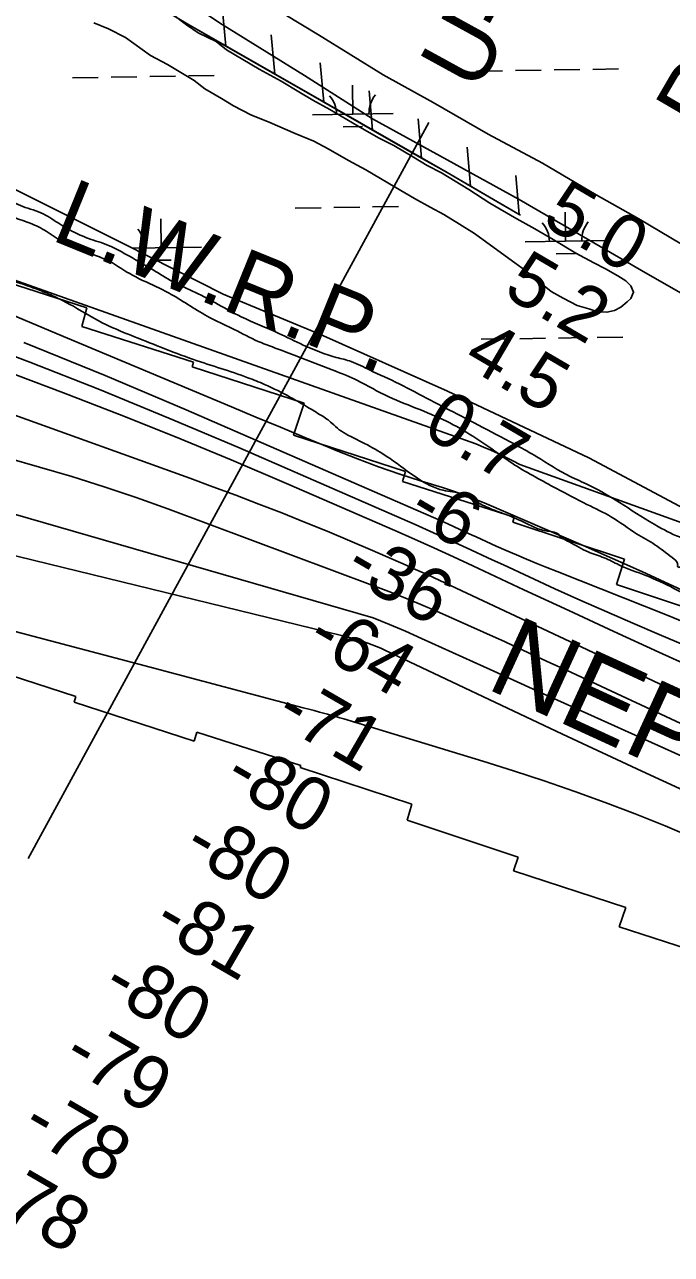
# Model space of a CAD drawing. Extents: x 3855477 to 3893699, y 299188 to 325115.
# Drawn here: x 3860091 to 3860894, y 316616 to 318142 of the extents above; entities that cross this region are included whole.
import ezdxf

# ---------------------------------------------------------------- set-up
doc = ezdxf.new("R2010")
doc.units = 0
for name, color, linetype in [('V-CHAN-NAID', 7, 'Continuous'), ('V-LEVE-TOET', 7, 'Continuous'), ('V-RIVR-EDGE', 7, 'Continuous'), ('V-RIVR-RANG', 7, 'Continuous'), ('V-RIVR-RANG-IDEN', 7, 'Continuous'), ('V-RRAP-FSHR', 7, 'Continuous'), ('V-RRAP-RVMT', 7, 'Continuous'), ('V-RRAP-RVMT-IDEN', 7, 'Continuous'), ('V-TOPO-DPTH', 7, 'Continuous'), ('V-TOPO-MAJR', 7, 'Continuous'), ('V-TOPO-MINR', 7, 'Continuous'), ('V-TOPO-SHOR', 7, 'Continuous'), ('V-TOPO-WATR', 7, 'Continuous'), ('V-TOPO-WATR-IDEN', 7, 'Continuous'), ('V-WETL-SWMP', 7, 'Continuous')]:
    doc.layers.add(name, color=color, linetype=linetype)

msp = doc.modelspace()

# ---------------------------------------------------------------- linework, layer by layer
at = {"layer": 'V-LEVE-TOET'}
for points in [[(3860906.5, 317869.1), (3860853.5, 317900.8), (3860800.4, 317930.4), (3860733.8, 317969.6), (3860666.5, 318005.7), (3860598.2, 318045), (3860536.2, 318079.5), (3860455.9, 318128.9), (3860372.4, 318180), (3860276.4, 318242.8), (3860194, 318291.7), (3860139.8, 318321.8), (3860102.5, 318340.2), (3860072.5, 318352.6), (3860019.4, 318370.1), (3859933.5, 318397.4), (3859855.1, 318425.7), (3859732.9, 318467.1), (3859678.2, 318484), (3859605.4, 318501.7), (3859553.3, 318515.5), (3859517.4, 318516.9), (3859513.2, 318517.2)], [(3859514.1, 318457), (3859544.7, 318456.4), (3859632.8, 318439.6), (3859717, 318409.2), (3859829.1, 318369.4), (3859948.7, 318332.3), (3860037.2, 318309.7), (3860100.9, 318287.9), (3860151.4, 318261.5), (3860238.5, 318206.7), (3860336.1, 318141.8), (3860438.5, 318078.4), (3860523, 318024.7), (3860615.5, 317974), (3860704.8, 317924.5), (3860792.5, 317873.9), (3860861.8, 317833.6), (3860920.6, 317800.2)]]:
    msp.add_lwpolyline(points, dxfattribs=at)
at = {"layer": 'V-RIVR-EDGE'}
for points in [[(3859519.3, 318133.3), (3859529.1, 318128.1), (3859557.8, 318117.3), (3859589.2, 318096.9), (3859608.3, 318091.7), (3859632.6, 318087.2), (3859655.7, 318083.2), (3859677.6, 318079.1), (3859695.1, 318076.3), (3859736.6, 318066.2), (3859764.5, 318061.4), (3859790.3, 318051.8), (3859824.2, 318038.5), (3859868.4, 318020.1), (3859890.7, 318012), (3859919.3, 318000.8), (3859946.4, 317985.2), (3859972.3, 317972.4), (3859987.4, 317966), (3859998.9, 317963.2), (3860007.3, 317958.4), (3860026.8, 317947.5), (3860045.9, 317937.5), (3860071.4, 317923.9), (3860094.9, 317913.9), (3860108.4, 317909.5), (3860130.3, 317897.1), (3860149.8, 317885.5), (3860170.5, 317876.3), (3860195.2, 317867.8), (3860221.1, 317854.2), (3860250.5, 317837.4), (3860275.2, 317822.6), (3860303, 317809.4), (3860359.6, 317779.3), (3860406.5, 317758.5), (3860436.8, 317744.1), (3860477.8, 317728.8), (3860496.5, 317723.6), (3860519.2, 317713.2), (3860555.8, 317696), (3860594.8, 317675.5), (3860632.3, 317656.3), (3860676.4, 317633.1), (3860726.6, 317605.5), (3860768, 317581.1), (3860790.7, 317570.6), (3860877.8, 317518.6), (3860907.7, 317504.6), (3860923.6, 317499.8), (3860947.5, 317491.7), (3860980.9, 317479.3), (3861011.2, 317471.3), (3861035.1, 317464.4), (3861065.4, 317456), (3861094, 317449.1), (3861112.8, 317445.1), (3861139.1, 317440.3), (3861167.3, 317430.2), (3861205.2, 317422.2), (3861236.2, 317418.9), (3861259.4, 317418), (3861273.7, 317417.2), (3861300, 317410), (3861325.9, 317397.5), (3861341.8, 317391.5), (3861353.7, 317387.9), (3861368.5, 317388.7), (3861377.7, 317388.7), (3861664.7, 317282.7), (3861681.1, 317276.7), (3861681.1, 317274.3), (3861687, 317270.7), (3861700.2, 317265.1), (3861705.7, 317256.7), (3861715.7, 317246.3), (3861721.2, 317241.5), (3861723.2, 317234.4), (3861726.4, 317227.6), (3861750.6, 317208), (3861757.4, 317197.6), (3861762.5, 317188.8), (3861767.3, 317187.2), (3861780.1, 317185.6), (3861788, 317178), (3861803.1, 317165.2), (3861810.3, 317151.6), (3861809.8, 317139.7), (3861814.2, 317132.9), (3861819.8, 317124.1), (3861817.3, 317108.6), (3861814.5, 317094.2), (3861799.4, 317086.7), (3861786.6, 317080.8), (3861777, 317076.8), (3861766.2, 317064.1), (3861761.8, 317062.9), (3861758.7, 317067.3), (3861753.9, 317083.2), (3861749.9, 317087.2), (3861742.8, 317089.6), (3861728.4, 317090.1), (3861720.1, 317091.3), (3861710.5, 317097.3), (3861701.4, 317107.7), (3861698.2, 317118), (3861695, 317124), (3861685.5, 317130.4), (3861670.3, 317131.3), (3861652.8, 317132.5), (3861648.4, 317134.1), (3861621.8, 317148.9), (3861610.2, 317154.5), (3861601.8, 317155.4), (3861592.3, 317158.2), (3861585.1, 317163.8), (3861576.8, 317171), (3861567.2, 317173.4), (3861541.3, 317180.2), (3861520.6, 317180.7), (3861509.8, 317179.9), (3861487.1, 317186.7), (3861457.3, 317196.8), (3861452.1, 317196), (3861445.3, 317191.2), (3861444.5, 317182.8), (3861448.1, 317178.4), (3861469.6, 317166.8), (3861511, 317148.8), (3861530.5, 317141.2), (3861552.8, 317132.4), (3861597, 317112.7)], [(3861161.1, 317323), (3861105.3, 317341.9), (3861095.4, 317346.7), (3861067.1, 317358.7), (3861040.4, 317369.2), (3861025.7, 317379.2), (3861011, 317386.8), (3860989.9, 317398.4), (3860974.8, 317402), (3860962, 317408), (3860930.6, 317424.4), (3860862.1, 317458.1), (3860828.7, 317471.3), (3860810.4, 317480.1), (3860790.5, 317487.3), (3860767, 317499.8), (3860758.6, 317504.6), (3860752.3, 317510.2), (3860744.3, 317512.6), (3860728, 317516.2), (3860714, 317522.6), (3860687.4, 317534.2), (3860666.2, 317542.3), (3860648.7, 317551.5), (3860633.2, 317559.5), (3860610.5, 317563.9), (3860578.7, 317578.7), (3860544.8, 317603.1), (3860519.8, 317618.3), (3860492.3, 317632.4), (3860481.6, 317638.8), (3860472.4, 317647.1), (3860466.1, 317652.3), (3860459.3, 317656.7), (3860442.2, 317667.1), (3860421.1, 317679.2), (3860388.8, 317695.2), (3860368.1, 317703.6), (3860300.8, 317726.1), (3860260.2, 317741.3), (3860222.8, 317756.2), (3860187.4, 317771.8), (3860146.4, 317795), (3860128.1, 317804.2), (3860109.4, 317812.2), (3860044.5, 317834.7), (3859988.3, 317859.6), (3859925.4, 317886.8), (3859887.6, 317901.3), (3859853.8, 317911.7), (3859831.9, 317919.7), (3859802.8, 317933), (3859772.9, 317945.8), (3859734.7, 317960.2), (3859695.3, 317982.6), (3859660.3, 318005.4), (3859631.2, 318017.5), (3859592.2, 318031.9), (3859552, 318048), (3859520.4, 318061)], [(3859768.4, 318041), (3859805.8, 318029), (3859833.7, 318015.8), (3859870.7, 318001.7), (3859904.6, 317989.3), (3859933.6, 317976.1), (3859963.5, 317964), (3859985, 317954), (3860008.5, 317939.6), (3860049.4, 317917.2), (3860076.9, 317902.8), (3860098, 317895.2), (3860117.9, 317885.2), (3860137.8, 317872.3), (3860159.3, 317862.3), (3860181.6, 317854.3), (3860199.9, 317845.9), (3860220.6, 317833.1), (3860254.8, 317816.3), (3860275.5, 317805.5), (3860323.7, 317776.6), (3860351.2, 317763.4), (3860381, 317748.6), (3860409.3, 317737.8), (3860435.2, 317727.7), (3860478.2, 317711.3), (3860508, 317698.1), (3860533.5, 317684.5), (3860610.3, 317651.6), (3860643.8, 317633.2), (3860673.2, 317613.6), (3860699.5, 317595.2), (3860724.9, 317580.4), (3860751.2, 317566), (3860789, 317546.3), (3860819.3, 317530.7), (3860850.7, 317509.9), (3860873.4, 317496.3), (3860894.9, 317480.3), (3860901.6, 317471.5), (3860901.6, 317468.7), (3860907.6, 317469.1), (3860918.7, 317465.1), (3860923.5, 317464.7), (3860931.5, 317464.7), (3860947.8, 317458.7), (3860971.7, 317449), (3860994.8, 317440.6), (3861011.5, 317433.4), (3861011.9, 317431.8), (3861012.3, 317422.2), (3861016.7, 317418.2), (3861031, 317413.8), (3861040.2, 317413.4), (3861052.9, 317411.8), (3861066.4, 317406.2), (3861070, 317402.6), (3861076, 317395), (3861087.9, 317391), (3861099.5, 317390.9), (3861115, 317393.3), (3861126.6, 317391.7), (3861145.7, 317385.6), (3861160.4, 317379.2), (3861170.4, 317373.6), (3861184.7, 317369.6), (3861204.2, 317363.6), (3861220.6, 317357.6), (3861237.3, 317348.7), (3861251.2, 317336.8), (3861264.7, 317323.6), (3861275, 317308.8), (3861281.8, 317303.2), (3861294.5, 317299.2), (3861313.6, 317284.4), (3861329.5, 317269.2), (3861363, 317248.4), (3861390, 317232.8), (3861398.4, 317228.8), (3861402.3, 317222.4), (3861399.9, 317218), (3861392.4, 317214.5), (3861387.2, 317215.3), (3861362.1, 317229.3), (3861300.4, 317260.5), (3861223.6, 317297.8), (3861161.1, 317323)]]:
    msp.add_spline(points, degree=3, dxfattribs=at)
at = {"layer": 'V-RIVR-RANG'}
msp.add_line((3860592.6, 318020.3), (3860095.2, 317106.9), dxfattribs=at)
at = {"layer": 'V-RRAP-FSHR'}
for p, q in [((3860340.8, 318115.1), (3860336.3, 318163.7)), ((3860401.5, 318080.3), (3860397.1, 318129)), ((3860462.3, 318045.6), (3860457.8, 318094.2)), ((3860523, 318010.8), (3860518.6, 318059.5)), ((3860583.8, 317976.1), (3860579.4, 318024.7)), ((3860644.5, 317941.1), (3860640.3, 317989.8)), ((3860705, 317906), (3860700.9, 317954.6))]:
    msp.add_line(p, q, dxfattribs=at)
for points in [[(3860705.6, 317905.7), (3860615.5, 317958), (3860293.4, 318142.2), (3860158, 318223.3), (3860080.4, 318260.2), (3859675.5, 318399.5)], [(3860340.8, 318115.1), (3860293.4, 318142.2), (3860280.2, 318150.1)], [(3860523, 318010.8), (3860462.3, 318045.6), (3860401.5, 318080.3), (3860340.8, 318115.1)], [(3860583.8, 317976.1), (3860523, 318010.8)], [(3860644.5, 317941.1), (3860615.5, 317958), (3860583.8, 317976.1)], [(3860705, 317906), (3860644.5, 317941.1)], [(3860706.4, 317905.2), (3860705, 317906)]]:
    msp.add_lwpolyline(points, dxfattribs=at)
at = {"layer": 'V-RRAP-RVMT'}
for p, q in [((3860168.2, 317790.2), (3860030.3, 317834.4)), ((3860162, 317766.9), (3860168.2, 317790.2)), ((3860300.5, 317723), (3860162, 317766.9)), ((3860299.1, 317716.9), (3860300.5, 317723)), ((3860438, 317672), (3860299.1, 317716.9)), ((3860424.7, 317632.1), (3860438, 317672)), ((3860563.9, 317587.1), (3860424.7, 317632.1)), ((3860559.9, 317574.8), (3860563.9, 317587.1)), ((3860698.7, 317530.4), (3860559.9, 317574.8)), ((3860696.9, 317524.5), (3860698.7, 317530.4)), ((3860835.4, 317478.4), (3860696.9, 317524.5)), ((3860825.7, 317446.9), (3860835.4, 317478.4)), ((3860963.3, 317401.2), (3860825.7, 317446.9)), ((3860025.9, 317349.7), (3860154.6, 317308.1)), ((3860154.6, 317308.1), (3860152.6, 317300.9)), ((3860152.6, 317300.9), (3860301.4, 317252.6)), ((3860301.4, 317252.6), (3860304.6, 317263.7)), ((3860304.6, 317263.7), (3860433.8, 317222.2)), ((3860433.8, 317222.2), (3860433.1, 317219.9)), ((3860433.1, 317219.9), (3860571.6, 317174.5)), ((3860571.6, 317174.5), (3860565.7, 317154.5)), ((3860565.7, 317154.5), (3860703.7, 317108.8)), ((3860703.7, 317108.8), (3860698, 317091.8)), ((3860698, 317091.8), (3860837.4, 317046.1)), ((3860837.4, 317046.1), (3860829.1, 317022.3)), ((3860829.1, 317022.3), (3860967.7, 316977.3))]:
    msp.add_line(p, q, dxfattribs=at)
at = {"layer": 'V-TOPO-DPTH'}
for points in [[(3860996.4, 317491.1), (3860705.7, 317595.9), (3860696.8, 317600.4), (3860687.8, 317604.9), (3860678.7, 317609.3), (3860669.6, 317613.5), (3860660.4, 317617.5), (3860651.2, 317621.4), (3859948.9, 317870.7), (3859911.2, 317883.8), (3859873.9, 317898), (3859836.7, 317912.6), (3859799.8, 317927.9), (3859763.2, 317943.7), (3859682.6, 317979.3), (3859669.4, 317985.2), (3859656.2, 317991.2), (3859643.1, 317997.2), (3859629.9, 318003.4), (3859520.7, 318042.9)], [(3860089.9, 317747.4), (3860190.9, 317706.1), (3860291.4, 317663.6), (3860586.2, 317535.5), (3860601.3, 317528.9), (3860616.4, 317522.1), (3860631.4, 317515.3), (3860646.4, 317508.3), (3860651.6, 317505.9), (3860664, 317500.2), (3860676.4, 317494.6), (3860688.9, 317489.1), (3860701.5, 317483.6), (3860714.1, 317478.3), (3860726.7, 317473.1), (3860739.4, 317467.9), (3860752.1, 317462.9), (3860888.5, 317409.1), (3860969, 317376)], [(3860089.9, 317747.4), (3860190.9, 317706.1), (3860291.4, 317663.6), (3860586.2, 317535.5), (3860601.3, 317528.9), (3860616.4, 317522.1), (3860631.4, 317515.3), (3860646.4, 317508.3), (3860651.6, 317505.9), (3860664, 317500.2), (3860676.4, 317494.6), (3860688.9, 317489.1), (3860701.5, 317483.6), (3860714.1, 317478.3), (3860726.7, 317473.1), (3860739.4, 317467.9), (3860752.1, 317462.9), (3860888.5, 317409.1), (3860969, 317376)], [(3860934.1, 317337.7), (3860878.1, 317363.1), (3860822.2, 317388.7), (3860766.4, 317414.5), (3860710.6, 317440.5), (3860647.2, 317470.2), (3860623.2, 317481.3), (3860599.1, 317492.3), (3860574.9, 317503.2), (3860550.6, 317513.8), (3860416, 317572.4), (3860347.3, 317601.7), (3860278.3, 317630.3), (3860208.9, 317657.8), (3860139.2, 317684.7), (3860079.9, 317707)], [(3860934.1, 317337.7), (3860878.1, 317363.1), (3860822.2, 317388.7), (3860766.4, 317414.5), (3860710.6, 317440.5), (3860647.2, 317470.2), (3860623.2, 317481.3), (3860599.1, 317492.3), (3860574.9, 317503.2), (3860550.6, 317513.8), (3860416, 317572.4), (3860347.3, 317601.7), (3860278.3, 317630.3), (3860208.9, 317657.8), (3860139.2, 317684.7), (3860079.9, 317707)], [(3860073, 317659.3), (3860296, 317578.7), (3860324.7, 317568.2), (3860353.2, 317557.6), (3860381.7, 317546.7), (3860410.1, 317535.7), (3860438.5, 317524.4), (3860466.7, 317513), (3860494.8, 317501.1), (3860522.8, 317489.1), (3860564.7, 317470.8), (3860573.4, 317467), (3860582, 317463.1), (3860590.6, 317459.2), (3860599.2, 317455.2), (3860774.9, 317372.8), (3860871.2, 317327.4), (3860967.5, 317281.9)], [(3860967.5, 317281.9), (3860871.2, 317327.4), (3860774.9, 317372.8), (3860599.2, 317455.2), (3860590.6, 317459.2), (3860582, 317463.1), (3860573.4, 317467), (3860564.7, 317470.8), (3860522.8, 317489.1), (3860494.8, 317501.1), (3860466.7, 317513), (3860438.5, 317524.4), (3860410.1, 317535.7), (3860381.7, 317546.7), (3860353.2, 317557.6), (3860324.7, 317568.2), (3860296, 317578.7), (3860073, 317659.3)], [(3860069.3, 317604), (3860109.6, 317592.6), (3860149.8, 317580.8), (3860189.7, 317568.3), (3860229.3, 317554.9), (3860268.7, 317540.7), (3860523.3, 317445.7), (3860543.1, 317438.1), (3860562.9, 317430.3), (3860582.6, 317422.2), (3860602.2, 317413.8), (3860621.7, 317405.3), (3860641.2, 317396.6), (3860660.6, 317387.9), (3860680, 317379.1), (3860682.1, 317378.1), (3860702.4, 317368.8), (3860722.8, 317359.4), (3860743.2, 317349.9), (3860763.5, 317340.5), (3860936.6, 317259.9)], [(3860936.6, 317259.9), (3860763.5, 317340.5), (3860743.2, 317349.9), (3860722.8, 317359.4), (3860702.4, 317368.8), (3860682.1, 317378.1), (3860680, 317379.1), (3860660.6, 317387.9), (3860641.2, 317396.6), (3860621.7, 317405.3), (3860602.2, 317413.8), (3860582.6, 317422.2), (3860562.9, 317430.3), (3860543.1, 317438.1), (3860523.3, 317445.7), (3860268.7, 317540.7), (3860229.3, 317554.9), (3860189.7, 317568.3), (3860149.8, 317580.8), (3860109.6, 317592.6), (3860069.3, 317604)]]:
    msp.add_lwpolyline(points, dxfattribs=at)
at = {"layer": 'V-TOPO-MAJR'}
msp.add_lwpolyline([(3860923.3, 317226.4), (3860860.8, 317254.5), (3860798.3, 317282.7), (3860735.8, 317311), (3860673.4, 317339.3), (3860583.7, 317380.1), (3860563.8, 317388.9), (3860543.8, 317397.4), (3860523.6, 317405.5), (3859722.8, 317636.8), (3859613.2, 317668.6), (3859526.2, 317695.4)], dxfattribs=at)
at = {"layer": 'V-TOPO-MINR'}
for points in [[(3860929.5, 317429.4), (3860857.2, 317462.9), (3860784.2, 317495.4), (3860664.5, 317547), (3860650.9, 317552.5), (3860637.3, 317557.8), (3860623.5, 317562.7), (3860609.6, 317567.2), (3860583.7, 317575.2), (3860556.9, 317583.9), (3860530.3, 317593.1), (3860504, 317603), (3860477.8, 317613.4), (3860469.2, 317616.9), (3860438.8, 317629.5), (3860408.5, 317642.1), (3860378.1, 317654.7), (3860347.8, 317667.4), (3860144.2, 317752.7), (3860060.3, 317787.7)], [(3860911, 317371.2), (3860878.5, 317385), (3860846.1, 317398.9), (3860813.8, 317413), (3860781.5, 317427.3), (3860749.3, 317441.7), (3860717.3, 317456.4), (3860685.3, 317471.3), (3860671.4, 317477.7), (3860639.5, 317492.5), (3860607.6, 317507), (3860575.6, 317521.3), (3860543.5, 317535.5), (3860355.6, 317617.2), (3860270, 317653.5), (3860184.1, 317688.9), (3860097.6, 317722.8), (3860010.7, 317755.7)], [(3860969, 317376), (3860888.5, 317409.1), (3860752.1, 317462.9), (3860739.4, 317467.9), (3860726.7, 317473.1), (3860714.1, 317478.3), (3860701.5, 317483.6), (3860688.9, 317489.1), (3860676.4, 317494.6), (3860664, 317500.2), (3860651.6, 317505.9), (3860646.4, 317508.3), (3860631.4, 317515.3), (3860616.4, 317522.1), (3860601.3, 317528.9), (3860586.2, 317535.5), (3860291.4, 317663.6), (3860190.9, 317706.1), (3860089.9, 317747.4)], [(3860934.1, 317337.7), (3860878.1, 317363.1), (3860822.2, 317388.7), (3860766.4, 317414.5), (3860710.6, 317440.5), (3860647.2, 317470.2), (3860623.2, 317481.3), (3860599.1, 317492.3), (3860574.9, 317503.2), (3860550.6, 317513.8), (3860416, 317572.4), (3860347.3, 317601.7), (3860278.3, 317630.3), (3860208.9, 317657.8), (3860139.2, 317684.7), (3860079.9, 317707)], [(3860967.5, 317281.9), (3860871.2, 317327.4), (3860774.9, 317372.8), (3860599.2, 317455.2), (3860590.6, 317459.2), (3860582, 317463.1), (3860573.4, 317467), (3860564.7, 317470.8), (3860522.8, 317489.1), (3860494.8, 317501.1), (3860466.7, 317513), (3860438.5, 317524.4), (3860410.1, 317535.7), (3860381.7, 317546.7), (3860353.2, 317557.6), (3860324.7, 317568.2), (3860296, 317578.7), (3860073, 317659.3)], [(3860955.8, 317169.7), (3860857.1, 317215.2), (3860758.7, 317261.2), (3860538.3, 317365.5), (3860533.1, 317367.8), (3860527.8, 317370.1), (3860522.5, 317372.2), (3860517.1, 317374.2), (3860503, 317379.3), (3859572.9, 317606.4), (3859527.4, 317619)], [(3860936.6, 317259.9), (3860763.5, 317340.5), (3860743.2, 317349.9), (3860722.8, 317359.4), (3860702.4, 317368.8), (3860682.1, 317378.1), (3860680, 317379.1), (3860660.6, 317387.9), (3860641.2, 317396.6), (3860621.7, 317405.3), (3860602.2, 317413.8), (3860582.6, 317422.2), (3860562.9, 317430.3), (3860543.1, 317438.1), (3860523.3, 317445.7), (3860268.7, 317540.7), (3860229.3, 317554.9), (3860189.7, 317568.3), (3860149.8, 317580.8), (3860109.6, 317592.6), (3860069.3, 317604)], [(3860922.9, 317131.9), (3860886, 317147.4), (3860848.8, 317162.2), (3860811.4, 317176.6), (3860773.8, 317190.2), (3860736, 317203.3), (3860697.9, 317215.8), (3860659.7, 317227.8), (3860487.1, 317280.1), (3860482.1, 317281.6), (3860477.1, 317283), (3860472, 317284.5), (3860467, 317285.9), (3860463.7, 317286.8), (3860457, 317288.7), (3860450.3, 317290.5), (3860443.6, 317292.4), (3860436.9, 317294.1), (3860246.7, 317344.4), (3860144.9, 317371.3), (3860043, 317398), (3859941.1, 317424.6), (3859839.1, 317451), (3859528.9, 317523.7)]]:
    msp.add_lwpolyline(points, dxfattribs=at)
at = {"layer": 'V-TOPO-SHOR'}
for points in [[(3860274.8, 318154.2), (3860292.1, 318141.4), (3860306.6, 318131.3), (3860328.7, 318120.8), (3860341.6, 318110.4), (3860382.1, 318086.3), (3860409.3, 318071.4), (3860431.3, 318058.1), (3860448.6, 318048), (3860469.8, 318036.3), (3860505.2, 318015.8), (3860530.4, 318001.3), (3860549.2, 317991.6), (3860573.6, 317977.1), (3860590.5, 317967), (3860608.6, 317957.8), (3860642.4, 317937.2), (3860668.4, 317920), (3860701.8, 317900.6), (3860724.2, 317888.1), (3860747, 317875.2), (3860775.3, 317858.3), (3860797.7, 317846.2), (3860811.9, 317838.6), (3860827.2, 317830.1), (3860837.4, 317823.7), (3860843.3, 317817.7), (3860846.8, 317809.7), (3860843.5, 317801.9), (3860838.8, 317797.6)], [(3860838.8, 317797.6), (3860831.2, 317790.9), (3860823.2, 317787), (3860813.7, 317784.8), (3860802.2, 317785.3), (3860791.2, 317789), (3860777, 317793.1), (3860759.3, 317802.3), (3860744.7, 317810.4), (3860729.1, 317822.8), (3860713, 317836), (3860699.6, 317846.1), (3860669.4, 317868.1), (3860649.4, 317882.6), (3860630.9, 317894.2), (3860611.2, 317905.9), (3860594.3, 317915.2), (3860575.1, 317926.1), (3860551.1, 317940.2), (3860514.5, 317961.5), (3860492.9, 317973.2), (3860467.7, 317987.7), (3860450, 317997), (3860426.8, 318006.7), (3860395.3, 318020.1), (3860371.6, 318029.8), (3860350.4, 318041.1), (3860335.5, 318050), (3860314.6, 318062), (3860301.3, 318072.5), (3860268.3, 318092.2), (3860247.4, 318103.5), (3860216.4, 318125.6), (3860195.2, 318136.5), (3860177, 318143.8)]]:
    msp.add_lwpolyline(points, dxfattribs=at)
at = {"layer": 'V-TOPO-WATR'}
msp.add_lwpolyline([(3860996.4, 317491.1), (3860705.7, 317595.9), (3860696.8, 317600.4), (3860687.8, 317604.9), (3860678.7, 317609.3), (3860669.6, 317613.5), (3860660.4, 317617.5), (3860651.2, 317621.4), (3859948.9, 317870.7), (3859911.2, 317883.8), (3859873.9, 317898), (3859836.7, 317912.6), (3859799.8, 317927.9), (3859763.2, 317943.7), (3859682.6, 317979.3), (3859669.4, 317985.2), (3859656.2, 317991.2), (3859643.1, 317997.2), (3859629.9, 318003.4), (3859520.7, 318042.9)], dxfattribs=at)
at = {"layer": 'V-WETL-SWMP'}
for p, q in [((3860150.3, 318075.6), (3860182.3, 318076.1)), ((3860198.3, 318076.4), (3860230.3, 318076.9)), ((3860246.3, 318077.2), (3860278.3, 318077.7)), ((3860294.3, 318078), (3860326.3, 318078.5)), ((3860652.1, 318083.8), (3860684.1, 318084.3)), ((3860700.1, 318084.6), (3860732.1, 318085.1)), ((3860748.1, 318085.4), (3860780.1, 318085.9)), ((3860796.1, 318086.1), (3860828.1, 318086.7)), ((3860498.4, 318030.5), (3860497.8, 318066.5)), ((3860448.4, 318029.7), (3860548.4, 318031.4)), ((3860486.6, 318014.9), (3860510.6, 318015.3)), ((3860215.6, 317868.7), (3860073.6, 317939.8)), ((3860426.9, 317913.9), (3860458.9, 317914.5)), ((3860474.9, 317914.7), (3860506.9, 317915.2)), ((3860522.9, 317915.5), (3860554.9, 317916)), ((3860762.4, 317873), (3860761.8, 317909)), ((3860260.6, 317864.8), (3860260, 317900.8)), ((3860337.4, 317807.4), (3860215.6, 317868.7)), ((3860224.6, 317864.2), (3860310.6, 317865.6)), ((3860712.4, 317872.2), (3860812.4, 317873.8)), ((3860254.3, 317849.3), (3860272.8, 317849.6)), ((3860750.7, 317857.3), (3860774.7, 317857.7)), ((3860458.2, 317757.2), (3860337.4, 317807.4)), ((3860615.7, 317687), (3860458.2, 317757.2)), ((3860801.5, 317753.5), (3860833.5, 317754)), ((3860657.5, 317751.2), (3860689.5, 317751.7)), ((3860705.5, 317752), (3860737.5, 317752.5)), ((3860753.5, 317752.7), (3860785.5, 317753.3)), ((3860791.2, 317604.2), (3860615.7, 317687)), ((3860954.8, 317517.1), (3860791.2, 317604.2))]:
    msp.add_line(p, q, dxfattribs=at)
for centre, start, end in [((3860443.1, 318030.1), 0.1615, 41.7052), ((3860553.6, 318031.9), 140.1615, 181.7052), ((3860707.2, 317872.5), 0.1615, 41.7052), ((3860817.7, 317874.3), 140.1615, 181.7052), ((3860205.3, 317864.4), 0.1615, 41.7052), ((3860315.8, 317866.2), 140.1615, 181.7052)]:
    msp.add_arc(centre, 35.2, start, end, dxfattribs=at)

# ---------------------------------------------------------------- texts
at = {"layer": 'V-CHAN-NAID'}
msp.add_text('NEPTUNE "24" (23.9)', height=100, rotation=59.1267, dxfattribs=at).set_placement((3860933.2, 315661.1))
at = {"layer": 'V-RIVR-RANG'}
for s, rotation, p in [('5.0', 329.6283, (3860731.1, 317894.6)), ('5.2', 329.6283, (3860683.2, 317806.8)), ('4.5', 329.6283, (3860632.9, 317720.4)), ('0.7', 329.6283, (3860582.5, 317634)), ('-6', 329.6283, (3860563.4, 317529.3)), ('-36', 329.9134, (3860484.7, 317459)), ('-64', 329.9134, (3860437.8, 317370.6)), ('-71', 329.9134, (3860398.9, 317277.6)), ('-80', 329.9134, (3860335.3, 317198.9)), ('-80', 329.9134, (3860284.9, 317112.5)), ('-81', 329.9134, (3860247.4, 317018.7)), ('-80', 329.9134, (3860184.3, 316939.7)), ('-79', 329.9134, (3860135.3, 316852.5)), ('-78', 329.9134, (3860084.3, 316766.5)), ('-78', 329.9134, (3860033.9, 316680)), ('-82', 329.9134, (3859981.3, 316595))]:
    msp.add_text(s, height=67, rotation=rotation, dxfattribs=at).set_placement(p)
at = {"layer": 'V-RIVR-RANG-IDEN'}
for s, rotation, p in [('U-020', 61.2863, (3860651.7, 318055.8)), ('R-24.2', 59.7717, (3860942.2, 317999.5))]:
    msp.add_text(s, height=83, rotation=rotation, dxfattribs=at).set_placement(p)
at = {"layer": 'V-RRAP-RVMT-IDEN'}
msp.add_text('NEPTUNE', height=100, rotation=335.3666, dxfattribs=at).set_placement((3860661.5, 317319))
at = {"layer": 'V-TOPO-WATR-IDEN'}
msp.add_text('L.W.R.P.', height=83, rotation=337.883, dxfattribs=at).set_placement((3860121.8, 317875.3))

doc.saveas('drawing.dxf')
